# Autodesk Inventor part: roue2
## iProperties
Author: Administrateur
Shininess: 20.0
PropertySet Name: _Private Model Information
Length Units: 11269
Angle Units: 11283
Time Units: 11279
Mass Units: 11290
Length Display Precision: 3
Angle Display Precision: 2
Compacted: False
Created: 2001-04
Part Number: roue2
Material: Par défaut
Document SubType Name: Modélisation
Designer: Administrateur
Control State: 0
Master: False
Checked Out: False
PropertySet Name: Design Tracking Control
Density: 0.0
Volumn: 0.0
Area: 0.0
PropertySet Name: Model Information
